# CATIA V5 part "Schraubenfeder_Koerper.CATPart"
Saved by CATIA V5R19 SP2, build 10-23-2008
Part number: Schraubendruckfeder ohne manuelle Korrektur der angelegten Windungen
Material "Stahl": density 7860 kg/m3, Young's modulus 2e+11 Pa, Poisson ratio 0.266, thermal expansion 1.17e-05 1/K
Bounding box of the stored display mesh (mm): x -59.997 to 59.997, y -59.996 to 60, z -20 to 167.5
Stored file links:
  C:\Users\wk\Documents\WHZ\CATIA_V5_FEM-Test\Schraubenfeder\Schraubenfeder_Koerper.CATPart
  C:\Program Files (x86)\Dassault Systemes\R19_SP2_lokal\intel_a\startup\materials\German\Catalog.CATMaterial
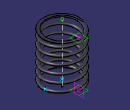
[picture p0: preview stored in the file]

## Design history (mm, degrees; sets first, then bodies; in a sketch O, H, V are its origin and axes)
Parameters
  Steigung_P = 25 mm
  Anzahl_federnde_Windungen = 5.5
  Drahtdurchmesser_d = 10 mm
  mittl_Federdurchmesser_klein = 110 mm
  mittl_Federdurchmesser_gross = 110 mm
  Konuswinkel = 0 deg {= atan((mittl_Federdurchmesser_gross -mittl_Federdurchmesser_klein)/2/(Anzahl_federnde_Windungen *Steigung_P )  )}
  Windungszahl_angelegte_Windungen = 0.75
Set1 "Geometrisches Set_Basiskonstr_3 Helix"
  Point1 "Startpunkt_federnde_Helix.1": (55 {= mittl_Federdurchmesser_gross /2}, 0, 0)
  Point2 "Mittelpunkt_Kreis_gross": (0, 0, 0)
  Line1 "Federachse": type PtDir, RefPoint Point2, Direction (0, 0, 1), Start -20 {= -2*Drahtdurchmesser_d}, Ende 167.5 {= Anzahl_federnde_Windungen *Steigung_P +3*Drahtdurchmesser_d}
  Helix1: Direction Line1, RefPoint Point1, Pitch 25 {= Steigung_P}, Height 137.5 {= Steigung_P *Anzahl_federnde_Windungen}, TaperAngle 0 {= Konuswinkel}
  Helix2 "Helix.2 angelegte Windung oben": Direction Line1, RefPoint vertex of Helix1, Pitch 5 {= 3.75mm*360/270}, Height 3.75 {= Drahtdurchmesser_d /2*Windungszahl_angelegte_Windungen}, TaperAngle 0 {= Konuswinkel}
  Helix3 "Helix.3 angelegte Windung unten": Direction Line1, RefPoint Point1, Pitch 5 {= 3.75mm*360/270}, Height 3.75 {= Drahtdurchmesser_d /2*Windungszahl_angelegte_Windungen}, TaperAngle 0
Set2 "GS Schraubenkurve komplett"
  Join1 "Verbindung 3 Helices": Elements (Helix3; Helix1; Helix2)
  CurveSmooth1 "Kurvenglättung": CurveToSmooth Join1, FixedEdges edge of Helix1
Set3 "Trennebenen_angelegte_Windungen Rippenprofil"
  Extremum1 "Äußerster Punkt angel. Helix oben": Reference Helix2, Direction (0, 0, 1), Direction2 (0, 0, 1), Direction3 (0, 0, 1)
  Plane1 "Trennebene oben": type OffsetPt, RefPlane xy-plane, RefPoint Extremum1
  Extremum2 "Äußerster Punkt angel. Helix unten": Reference Helix3, Direction (0, 0, 1), Direction2 (0, 0, 1), Direction3 (0, 0, 1)
  Plane2 "Trennebene unten": type OffsetPt, RefPlane xy-plane, RefPoint Extremum2
  Plane3 "Ebene_Rippenprofil": type Normal, Curve CurveSmooth1, RefPoint Extremum2
  Circle1 "Kreis für \"Rippe\"": type CtrRad, Start 0, End 180, Center Extremum2, Support Plane3, Radius 5 {= Drahtdurchmesser_d /2}, FirstDirection (0, 1, 0)
  Extremum3 "Äußerster Punkt Federachse": Reference Line1, Direction (0, 0, 1), Direction2 (0, 0, 1), Direction3 (0, 0, 1)
Body1 (main body), material "Stahl"
  Rib1: profile Circle1, centre curve CurveSmooth1
  Split1: SplitPlane Plane1
  Split2: SplitPlane Plane2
